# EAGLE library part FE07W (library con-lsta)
FEMALE HEADER
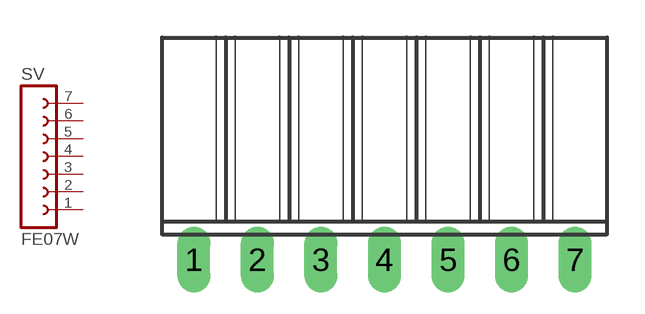
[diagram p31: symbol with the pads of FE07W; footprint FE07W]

Designator prefix SV

## FE07W (OC_FARNELL: unknown; OC_NEWARK: unknown)  [FE07W]
1  1  pas
2  2  pas
3  3  pas
4  4  pas
5  5  pas
6  6  pas
7  7  pas

## Footprint FE07W (pad centres in mm)
FEMALE HEADER
drill 0.813 long: 1 -7.62,0; 2 -5.08,0; 3 -2.54,0; 4 0,0; 5 2.54,0; 6 5.08,0; 7 7.62,0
